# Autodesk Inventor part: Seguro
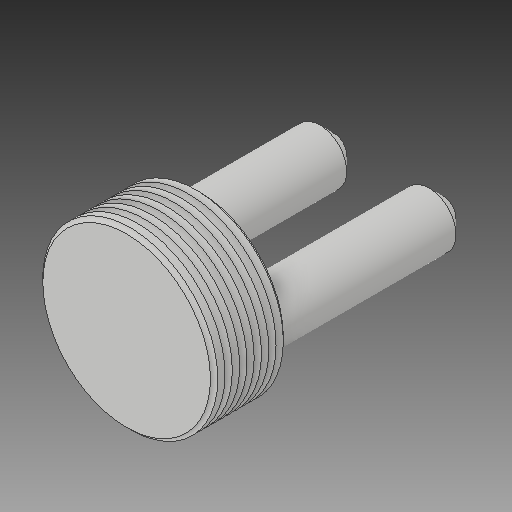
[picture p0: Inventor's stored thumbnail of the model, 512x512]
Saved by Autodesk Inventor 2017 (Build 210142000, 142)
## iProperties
Part Number: Seguro
Material: Genérico
Document SubType Name: Modeling
Designer: Diego
Density: 1 g/cm^3
Appearance: Valor por defecto
Author: Diego
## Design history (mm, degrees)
derived "Lubina.ipt"
feature "Seguro::Lubina.ipt" dims "d0" = 10
tag "OperaciónIdentificador1"
node "Sólido1"
